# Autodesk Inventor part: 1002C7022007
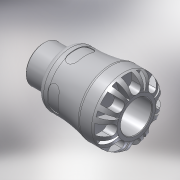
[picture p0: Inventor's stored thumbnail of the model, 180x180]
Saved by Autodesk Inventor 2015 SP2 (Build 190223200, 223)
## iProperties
Created: 2016-12
Part Number: 1002C7022007
Material: PVC-Piping
Description: PLASSON MALE COPPER ADAPTOR 22X3/4" SERIES 1
Document SubType Name: Modeling
Designer: KIM
Mass: 78.119 g
Surface Area: 135.648 cm^2
Volume: 55.7993 cm^3
Density: 1.4 g/cm^3
Appearance: Smooth - White
Author: KIM
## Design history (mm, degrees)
derived "1002С.ipt"
feature "Solid1::1002С.ipt"
tag "TaggingFeature1"
body "Solid1"
other parameters: "d0" = 76, "d1" = 20.16, "d2" = 22, "d3" = 28.2, "d4" = 47, "d6" = 48, "d8" = 39.95, "d13" = 7.52, "d14" = 7.52, "d15" = 0, "d17" = 360 deg, "d19" = 8 deg, "d20" = 0.44, "d21" = 0.44, "d22" = 8 deg, "d24" = 0, "d26" = 360 deg, "d32" = 4.7, "d33" = 4.7, "d34" = 26.441, "d35" = 2.75, "d38" = 17, "d39" = 0.79323, "d42" = 7.99, "d43" = 5.17, "d45" = 15.288, "d46" = 0, "d59" = 360 deg, "d62" = 6.7915, "d63" = 0.44, "d65" = 0, "d66" = 0.47, "d_" = 22, "E_" = 47, "H_" = 76, "l_" = 48, "R_" = 26.441, "l_2" = 17, "d9" = 9.4, "d11" = 47, "d12" = 28.2
